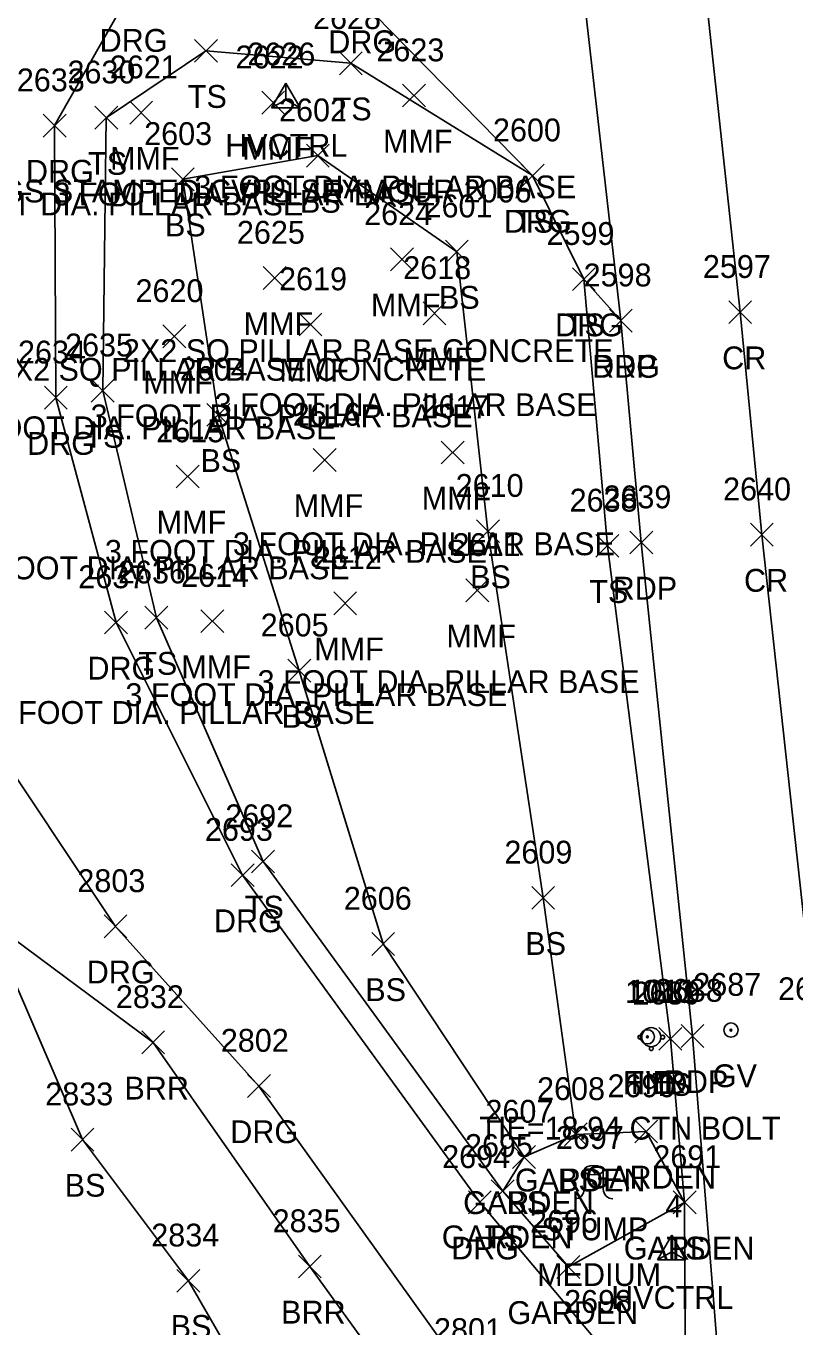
# Model space of a CAD drawing. Extents: x 1461855 to 1464118, y 556196 to 557441.
# Drawn here: x 1462324.1 to 1462391.4, y 556761.6 to 556875.5 of the extents above; entities that cross this region are included whole.
import ezdxf

# ---------------------------------------------------------------- set-up
doc = ezdxf.new("R2010")
doc.units = 0
for name, color, linetype in [('C_A', 7, 'Continuous'), ('C_C', 7, 'Continuous'), ('C_I', 7, 'Continuous'), ('CBP', 7, 'Continuous'), ('CPSM', 7, 'Continuous'), ('L_A', 7, 'Continuous'), ('L_C', 7, 'Continuous'), ('L_I', 7, 'Continuous'), ('L_TIC', 7, 'Continuous'), ('LABL', 7, 'Continuous'), ('LAPB', 7, 'Continuous'), ('LELB', 7, 'Continuous'), ('LTS', 7, 'Continuous'), ('P_A', 7, 'Continuous'), ('P_I', 7, 'Continuous'), ('P_TIC', 7, 'Continuous'), ('PET', 7, 'Continuous'), ('PRC', 7, 'Continuous'), ('R_A', 7, 'Continuous'), ('R_I', 7, 'Continuous'), ('R_TIC', 7, 'Continuous'), ('RDG', 7, 'Continuous'), ('U_A', 7, 'Continuous'), ('U_I', 7, 'Continuous'), ('UWFH', 7, 'Continuous'), ('UWV', 7, 'Continuous')]:
    doc.layers.add(name, color=color, linetype=linetype)

msp = doc.modelspace()

# ---------------------------------------------------------------- linework, layer by layer
at = {"layer": 'CBP'}
for radius in [0.625, 0.0833]:
    msp.add_circle((1462378.47, 556787.02), radius, dxfattribs=at)
at = {"layer": 'CPSM'}
for p, q in [((1462345.56, 556868.36), (1462346.81, 556870.52)), ((1462348.06, 556868.36), (1462346.81, 556870.52)), ((1462346.81, 556869.08), (1462346.81, 556870.52)), ((1462345.56, 556868.36), (1462346.81, 556869.08)), ((1462346.81, 556869.08), (1462346.81, 556869.08)), ((1462346.81, 556869.08), (1462348.06, 556868.36)), ((1462345.56, 556868.36), (1462348.06, 556868.36)), ((1462379.35, 556767.48), (1462380.6, 556769.65)), ((1462379.35, 556767.48), (1462380.6, 556769.65)), ((1462381.85, 556767.48), (1462380.6, 556769.65)), ((1462380.6, 556768.2), (1462380.6, 556769.65)), ((1462381.85, 556767.48), (1462380.6, 556769.65)), ((1462380.6, 556768.2), (1462380.6, 556769.65)), ((1462379.35, 556767.48), (1462380.6, 556768.2)), ((1462379.35, 556767.48), (1462380.6, 556768.2)), ((1462379.35, 556767.48), (1462381.85, 556767.48)), ((1462379.35, 556767.48), (1462381.85, 556767.48)), ((1462380.6, 556768.2), (1462380.6, 556768.2)), ((1462380.6, 556768.2), (1462381.85, 556767.48)), ((1462380.6, 556768.2), (1462380.6, 556768.2)), ((1462380.6, 556768.2), (1462381.85, 556767.48))]:
    msp.add_line(p, q, dxfattribs=at)
at = {"layer": 'L_TIC'}
for points in [[(1462338.82, 556872.36), (1462340.82, 556874.36)], [(1462340.82, 556872.36), (1462338.82, 556874.36)], [(1462351.5, 556871.27), (1462353.5, 556873.27)], [(1462353.5, 556871.27), (1462351.5, 556873.27)], [(1462344.71, 556867.82), (1462346.71, 556869.82)], [(1462346.71, 556867.82), (1462344.71, 556869.82)], [(1462357.04, 556868.44), (1462359.04, 556870.44)], [(1462359.04, 556868.44), (1462357.04, 556870.44)], [(1462330.09, 556866.5), (1462332.09, 556868.5)], [(1462332.09, 556866.5), (1462330.09, 556868.5)], [(1462333.14, 556866.95), (1462335.14, 556868.95)], [(1462335.14, 556866.95), (1462333.14, 556868.95)], [(1462348.61, 556863.18), (1462350.61, 556865.18)], [(1462350.61, 556863.18), (1462348.61, 556865.18)], [(1462336.79, 556861.11), (1462338.79, 556863.11)], [(1462338.79, 556861.11), (1462336.79, 556863.11)], [(1462367.42, 556861.43), (1462369.42, 556863.43)], [(1462369.42, 556861.43), (1462367.42, 556863.43)], [(1462355.98, 556854.1), (1462357.98, 556856.1)], [(1462357.98, 556854.1), (1462355.98, 556856.1)], [(1462360.78, 556854.77), (1462362.78, 556856.77)], [(1462362.78, 556854.77), (1462360.78, 556856.77)], [(1462360.78, 556854.77), (1462362.78, 556856.77)], [(1462362.78, 556854.77), (1462360.78, 556856.77)], [(1462344.84, 556852.47), (1462346.84, 556854.47)], [(1462346.84, 556852.47), (1462344.84, 556854.47)], [(1462371.91, 556852.36), (1462373.91, 556854.36)], [(1462373.91, 556852.36), (1462371.91, 556854.36)], [(1462347.97, 556848.39), (1462349.97, 556850.39)], [(1462349.97, 556848.39), (1462347.97, 556850.39)], [(1462358.83, 556849.37), (1462360.83, 556851.37)], [(1462360.83, 556849.37), (1462358.83, 556851.37)], [(1462336.05, 556847.35), (1462338.05, 556849.35)], [(1462338.05, 556847.35), (1462336.05, 556849.35)], [(1462329.78, 556842.6), (1462331.78, 556844.6)], [(1462331.78, 556842.6), (1462329.78, 556844.6)], [(1462339.9, 556840.48), (1462341.9, 556842.48)], [(1462341.9, 556840.48), (1462339.9, 556842.48)], [(1462360.42, 556837.19), (1462362.42, 556839.19)], [(1462362.42, 556837.19), (1462360.42, 556839.19)], [(1462349.21, 556836.53), (1462351.21, 556838.53)], [(1462351.21, 556836.53), (1462349.21, 556838.53)], [(1462337.21, 556835.08), (1462339.21, 556837.08)], [(1462339.21, 556835.08), (1462337.21, 556837.08)], [(1462363.51, 556830.3), (1462365.51, 556832.3)], [(1462365.51, 556830.3), (1462363.51, 556832.3)], [(1462363.51, 556830.3), (1462365.51, 556832.3)], [(1462365.51, 556830.3), (1462363.51, 556832.3)], [(1462373.97, 556829.01), (1462375.97, 556831.01)], [(1462375.97, 556829.01), (1462373.97, 556831.01)], [(1462362.58, 556825.12), (1462364.58, 556827.12)], [(1462364.58, 556825.12), (1462362.58, 556827.12)], [(1462351.01, 556823.98), (1462353.01, 556825.98)], [(1462353.01, 556823.98), (1462351.01, 556825.98)], [(1462334.48, 556822.72), (1462336.48, 556824.72)], [(1462336.48, 556822.72), (1462334.48, 556824.72)], [(1462339.38, 556822.42), (1462341.38, 556824.42)], [(1462341.38, 556822.42), (1462339.38, 556824.42)], [(1462346.99, 556818.08), (1462348.99, 556820.08)], [(1462348.99, 556818.08), (1462346.99, 556820.08)], [(1462343.82, 556801.37), (1462345.82, 556803.37)], [(1462345.82, 556801.37), (1462343.82, 556803.37)], [(1462368.34, 556798.19), (1462370.34, 556800.19)], [(1462370.34, 556798.19), (1462368.34, 556800.19)], [(1462354.33, 556794.15), (1462356.33, 556796.15)], [(1462356.33, 556794.15), (1462354.33, 556796.15)], [(1462379.48, 556785.85), (1462381.48, 556787.85)], [(1462381.48, 556785.85), (1462379.48, 556787.85)], [(1462334.19, 556785.53), (1462336.19, 556787.53)], [(1462336.19, 556785.53), (1462334.19, 556787.53)], [(1462377.37, 556777.73), (1462379.37, 556779.73)], [(1462379.37, 556777.73), (1462377.37, 556779.73)], [(1462328.01, 556777.02), (1462330.01, 556779.02)], [(1462330.01, 556777.02), (1462328.01, 556779.02)], [(1462371.2, 556777.48), (1462373.2, 556779.48)], [(1462373.2, 556777.48), (1462371.2, 556779.48)], [(1462371.2, 556777.48), (1462373.2, 556779.48)], [(1462373.2, 556777.48), (1462371.2, 556779.48)], [(1462366.67, 556775.5), (1462368.67, 556777.5)], [(1462368.67, 556775.5), (1462366.67, 556777.5)], [(1462366.67, 556775.5), (1462368.67, 556777.5)], [(1462368.67, 556775.5), (1462366.67, 556777.5)], [(1462366.67, 556775.5), (1462368.67, 556777.5)], [(1462368.67, 556775.5), (1462366.67, 556777.5)], [(1462364.8, 556772.5), (1462366.8, 556774.5)], [(1462366.8, 556772.5), (1462364.8, 556774.5)], [(1462364.8, 556772.5), (1462366.8, 556774.5)], [(1462366.8, 556772.5), (1462364.8, 556774.5)], [(1462380.73, 556771.52), (1462382.73, 556773.52)], [(1462382.73, 556771.52), (1462380.73, 556773.52)], [(1462380.73, 556771.52), (1462382.73, 556773.52)], [(1462382.73, 556771.52), (1462380.73, 556773.52)], [(1462347.92, 556765.91), (1462349.92, 556767.91)], [(1462349.92, 556765.91), (1462347.92, 556767.91)], [(1462370.55, 556765.87), (1462372.55, 556767.87)], [(1462372.55, 556765.87), (1462370.55, 556767.87)], [(1462370.55, 556765.87), (1462372.55, 556767.87)], [(1462372.55, 556765.87), (1462370.55, 556767.87)], [(1462337.28, 556764.66), (1462339.28, 556766.66)], [(1462339.28, 556764.66), (1462337.28, 556766.66)]]:
    msp.add_lwpolyline(points, dxfattribs=at)
at = {"layer": 'LABL'}
msp.add_lwpolyline([(1462266.97, 556912.47), (1462274.52, 556891.23), (1462280.07, 556865.7), (1462289.54, 556828.05), (1462304.73, 556803.64), (1462320.72, 556797.25), (1462335.19, 556786.53), (1462348.92, 556766.91), (1462363.68, 556746.45), (1462353.82, 556738.72), (1462344.08, 556725.82), (1462329.22, 556725.69), (1462313.32, 556709.65), (1462319.88, 556687.65), (1462319.87, 556671.79), (1462309.53, 556658.61)], dxfattribs=at)
at = {"layer": 'LAPB'}
for points in [[(1462367.67, 556776.5), (1462372.2, 556778.48), (1462378.37, 556778.73), (1462381.73, 556772.52), (1462371.55, 556766.87)], [(1462367.67, 556776.5), (1462365.8, 556773.5), (1462371.55, 556766.87)]]:
    msp.add_lwpolyline(points, dxfattribs=at)
at = {"layer": 'LELB'}
for points in [[(1462298.79, 556927.09), (1462302.53, 556917.21), (1462305.12, 556905.68), (1462302.57, 556876.56), (1462305.98, 556856.21), (1462308.29, 556833.25), (1462314.59, 556815.41), (1462320.72, 556797.25), (1462329.01, 556778.02), (1462338.28, 556765.66), (1462353.82, 556738.72), (1462367.21, 556725.65), (1462382.15, 556699.86)], [(1462368.42, 556862.43), (1462352.5, 556872.27), (1462339.82, 556873.36), (1462331.09, 556867.5), (1462330.78, 556843.6), (1462335.48, 556823.72), (1462344.82, 556802.37), (1462365.8, 556773.5)], [(1462361.78, 556855.77), (1462349.61, 556864.18), (1462337.79, 556862.11), (1462340.9, 556841.48), (1462347.99, 556819.08), (1462355.33, 556795.15), (1462367.67, 556776.5)], [(1462361.78, 556855.77), (1462364.51, 556831.3)], [(1462372.91, 556853.36), (1462374.97, 556830.01), (1462380.48, 556786.85), (1462381.73, 556772.52), (1462381.8, 556754.73)], [(1462372.2, 556778.48), (1462369.34, 556799.19), (1462364.51, 556831.3)]]:
    msp.add_lwpolyline(points, dxfattribs=at)
at = {"layer": 'LTS'}
for p, q in [((1462372.94, 556775.34), (1462372.94, 556773.67)), ((1462374.6, 556775.17), (1462374.6, 556775.34)), ((1462374.6, 556775.34), (1462374.6, 556773.67)), ((1462373.77, 556774.2), (1462373.77, 556774.2)), ((1462373.77, 556774.2), (1462373.77, 556774.2)), ((1462373.77, 556774.17), (1462373.77, 556774.17))]:
    msp.add_line(p, q, dxfattribs=at)
msp.add_circle((1462373.77, 556774.2), 0.0833, dxfattribs=at)
for centre, start, end in [((1462372.1, 556773.67), 270, 360), ((1462375.44, 556773.67), 180, 270)]:
    msp.add_arc(centre, 0.833, start, end, dxfattribs=at)
msp.add_ellipse((1462373.77, 556775.34), major_axis=(-0.833, 0), ratio=0.5, dxfattribs=at)
at = {"layer": 'P_TIC'}
for points in [[(1462385.59, 556849.47), (1462387.59, 556851.47)], [(1462387.59, 556849.47), (1462385.59, 556851.47)], [(1462375.15, 556848.73), (1462377.15, 556850.73)], [(1462377.15, 556848.73), (1462375.15, 556850.73)], [(1462376.94, 556829.3), (1462378.94, 556831.3)], [(1462378.94, 556829.3), (1462376.94, 556831.3)], [(1462387.49, 556829.99), (1462389.49, 556831.99)], [(1462389.49, 556829.99), (1462387.49, 556831.99)], [(1462381.42, 556786.09), (1462383.42, 556788.09)], [(1462383.42, 556786.09), (1462381.42, 556788.09)]]:
    msp.add_lwpolyline(points, dxfattribs=at)
at = {"layer": 'PET'}
msp.add_lwpolyline([(1462362.03, 557020.04), (1462364.05, 556983.23), (1462364.4, 556972.86), (1462366.43, 556947.21), (1462369.72, 556911.82), (1462372.49, 556881.81), (1462376.15, 556849.73), (1462377.94, 556830.3), (1462382.42, 556787.09), (1462384.86, 556756.35), (1462386.15, 556741.35), (1462389.31, 556702.38), (1462390.63, 556682.52), (1462394.11, 556641.35), (1462397.73, 556598.46)], dxfattribs=at)
at = {"layer": 'PRC'}
msp.add_lwpolyline([(1462372.67, 557021), (1462375.13, 556983.57), (1462377.28, 556947.87), (1462380.67, 556912.86), (1462383.06, 556883.19), (1462386.59, 556850.47), (1462388.49, 556830.99), (1462393.27, 556787.23), (1462396.72, 556743.28), (1462399.49, 556711.38), (1462401.67, 556680.3), (1462405.06, 556640.86), (1462409.08, 556598.37)], dxfattribs=at)
at = {"layer": 'R_TIC'}
for points in [[(1462325.57, 556865.81), (1462327.57, 556867.81)], [(1462327.57, 556865.81), (1462325.57, 556867.81)], [(1462367.42, 556861.43), (1462369.42, 556863.43)], [(1462369.42, 556861.43), (1462367.42, 556863.43)], [(1462371.91, 556852.36), (1462373.91, 556854.36)], [(1462373.91, 556852.36), (1462371.91, 556854.36)], [(1462375.15, 556848.73), (1462377.15, 556850.73)], [(1462377.15, 556848.73), (1462375.15, 556850.73)], [(1462325.67, 556841.98), (1462327.67, 556843.98)], [(1462327.67, 556841.98), (1462325.67, 556843.98)], [(1462330.95, 556822.3), (1462332.95, 556824.3)], [(1462332.95, 556822.3), (1462330.95, 556824.3)], [(1462342.03, 556800.18), (1462344.03, 556802.18)], [(1462344.03, 556800.18), (1462342.03, 556802.18)], [(1462330.9, 556795.69), (1462332.9, 556797.69)], [(1462332.9, 556795.69), (1462330.9, 556797.69)], [(1462343.46, 556781.71), (1462345.46, 556783.71)], [(1462345.46, 556781.71), (1462343.46, 556783.71)], [(1462362.8, 556771.53), (1462364.8, 556773.53)], [(1462364.8, 556771.53), (1462362.8, 556773.53)]]:
    msp.add_lwpolyline(points, dxfattribs=at)
at = {"layer": 'RDG'}
for points in [[(1462389.31, 556702.38), (1462382.82, 556722.74), (1462375.16, 556739.02), (1462362.56, 556757.38), (1462344.46, 556782.71), (1462331.9, 556796.69), (1462320.22, 556814.15), (1462314.76, 556835.2), (1462311.82, 556859.76), (1462312.08, 556892.51), (1462314.63, 556919.62), (1462308.29, 556930.67)], [(1462376.15, 556849.73), (1462372.91, 556853.36), (1462368.42, 556862.43), (1462353.04, 556878.15), (1462343.64, 556880.74), (1462333.03, 556878.27), (1462326.57, 556866.81), (1462326.67, 556842.98), (1462331.95, 556823.3), (1462343.03, 556801.18), (1462363.8, 556772.53), (1462374.49, 556759.85), (1462381.8, 556754.73), (1462384.86, 556756.35)]]:
    msp.add_lwpolyline(points, dxfattribs=at)
at = {"layer": 'UWFH'}
msp.add_line((1462378.81, 556786.99), (1462378.81, 556786.99), dxfattribs=at)
for centre, radius in [((1462378.81, 556786.99), 0.833), ((1462377.81, 556786.99), 0.167), ((1462379.81, 556786.99), 0.167), ((1462378.81, 556785.99), 0.167)]:
    msp.add_circle(centre, radius, dxfattribs=at)
at = {"layer": 'UWV'}
for radius in [0.625, 0.0833]:
    msp.add_circle((1462385.79, 556787.61), radius, dxfattribs=at)

# ---------------------------------------------------------------- texts
at = {"layer": 'C_A'}
for s, p in [('HVCTRL', (1462341.5, 556864.08)), ('TIE', (1462376.55, 556782.02)), ('HVCTRL', (1462375.3, 556763.2)), ('HVCTRL', (1462375.3, 556763.2))]:
    msp.add_text(s, height=2, dxfattribs=at).set_placement(p)
at = {"layer": 'C_C'}
for s, p in [('VTGS STAMPED CVPS SEYMOUR 2006', (1462318.39, 556860.08)), ('TIE=18.94 CTN BOLT', (1462363.75, 556778.02))]:
    msp.add_text(s, height=2, dxfattribs=at).set_placement(p)
at = {"layer": 'C_I'}
for s, p in [('2626', (1462343.44, 556872.08)), ('1011', (1462376.83, 556790.02)), ('4', (1462380.04, 556771.2)), ('4', (1462380.04, 556771.2))]:
    msp.add_text(s, height=2, dxfattribs=at).set_placement(p)
at = {"layer": 'L_A'}
for s, p in [('TS', (1462338.23, 556868.36)), ('TS', (1462350.91, 556867.27)), ('MMF', (1462355.33, 556864.44)), ('MMF', (1462343, 556863.82)), ('TS', (1462329.5, 556862.5)), ('MMF', (1462331.42, 556862.95)), ('BS', (1462348.05, 556859.18)), ('TS', (1462366.83, 556857.43)), ('BS', (1462336.23, 556857.11)), ('BS', (1462360.22, 556850.77)), ('BS', (1462360.22, 556850.77)), ('MMF', (1462354.26, 556850.1)), ('MMF', (1462343.12, 556848.47)), ('TS', (1462371.32, 556848.36)), ('MMF', (1462357.11, 556845.37)), ('MMF', (1462346.25, 556844.39)), ('MMF', (1462334.33, 556843.35)), ('TS', (1462329.19, 556838.6)), ('BS', (1462339.34, 556836.48)), ('MMF', (1462347.5, 556832.53)), ('MMF', (1462358.71, 556833.19)), ('MMF', (1462335.5, 556831.08)), ('BS', (1462362.95, 556826.3)), ('BS', (1462362.95, 556826.3)), ('TS', (1462373.38, 556825.01)), ('MMF', (1462360.87, 556821.12)), ('MMF', (1462349.3, 556819.98)), ('TS', (1462333.89, 556818.72)), ('MMF', (1462337.66, 556818.42)), ('BS', (1462346.44, 556814.08)), ('TS', (1462343.22, 556797.37)), ('BS', (1462367.78, 556794.19)), ('BS', (1462353.77, 556790.15)), ('BRR', (1462332.68, 556781.53)), ('TS', (1462378.89, 556781.85)), ('GARDEN', (1462366.87, 556773.48)), ('BS', (1462370.64, 556773.48)), ('GARDEN', (1462373.04, 556773.73)), ('BS', (1462327.45, 556773.02)), ('GARDEN', (1462362.34, 556771.5)), ('GARDEN', (1462362.34, 556771.5)), ('BS', (1462366.12, 556771.5)), ('GARDEN', (1462360.47, 556768.5)), ('TS', (1462364.21, 556768.5)), ('STUMP', (1462369.19, 556769.2)), ('GARDEN', (1462376.4, 556767.52)), ('TS', (1462380.14, 556767.52)), ('BRR', (1462346.4, 556761.91)), ('GARDEN', (1462366.22, 556761.87)), ('GARDEN', (1462366.22, 556761.87)), ('BS', (1462336.73, 556760.66))]:
    msp.add_text(s, height=2, dxfattribs=at).set_placement(p)
at = {"layer": 'L_C'}
for s, p in [('3 FOOT DIA. PILLAR BASE', (1462326.47, 556859.82)), ('3 FOOT DIA. PILLAR BASE', (1462338.8, 556860.44)), ('3 FOOT DIA. PILLAR BASE', (1462314.9, 556858.95)), ('2X2 SQ PILLAR BASE CONCRETE', (1462332.55, 556846.1)), ('2X2 SQ PILLAR BASE CONCRETE', (1462321.41, 556844.47)), ('3 FOOT DIA. PILLAR BASE', (1462329.72, 556840.39)), ('3 FOOT DIA. PILLAR BASE', (1462340.58, 556841.37)), ('3 FOOT DIA. PILLAR BASE', (1462317.8, 556839.35)), ('3 FOOT DIA. PILLAR BASE', (1462342.18, 556829.19)), ('3 FOOT DIA. PILLAR BASE', (1462330.97, 556828.53)), ('3 FOOT DIA. PILLAR BASE', (1462318.97, 556827.08)), ('3 FOOT DIA. PILLAR BASE', (1462344.34, 556817.12)), ('3 FOOT DIA. PILLAR BASE', (1462332.77, 556815.98)), ('3 FOOT DIA. PILLAR BASE', (1462321.14, 556814.42)), ('MEDIUM', (1462368.82, 556765.2))]:
    msp.add_text(s, height=2, dxfattribs=at).set_placement(p)
at = {"layer": 'L_I'}
for s, p in [('2628', (1462349.19, 556875.27)), ('2623', (1462354.74, 556872.44)), ('2622', (1462342.41, 556871.82)), ('2630', (1462327.69, 556870.5)), ('2621', (1462331.4, 556870.95)), ('2602', (1462346.22, 556867.18)), ('2600', (1462364.95, 556865.43)), ('2603', (1462334.41, 556865.11)), ('2601', (1462358.96, 556858.77)), ('2601', (1462358.96, 556858.77)), ('2624', (1462353.67, 556858.1)), ('2625', (1462342.53, 556856.47)), ('2599', (1462369.64, 556856.36)), ('2618', (1462357.09, 556853.37)), ('2619', (1462346.22, 556852.39)), ('2620', (1462333.65, 556851.35)), ('2635', (1462327.48, 556846.6)), ('2604', (1462337.52, 556844.48)), ('2616', (1462347.42, 556840.53)), ('2617', (1462358.68, 556841.19)), ('2615', (1462335.47, 556839.08)), ('2610', (1462361.68, 556834.3)), ('2610', (1462361.68, 556834.3)), ('2638', (1462371.66, 556833.01)), ('2611', (1462361.41, 556829.12)), ('2612', (1462349.27, 556827.98)), ('2636', (1462332.12, 556826.72)), ('2614', (1462337.64, 556826.42)), ('2605', (1462344.61, 556822.08)), ('2692', (1462341.51, 556805.37)), ('2609', (1462365.95, 556802.19)), ('2606', (1462351.89, 556798.15)), ('2832', (1462331.93, 556789.53)), ('2689', (1462377.17, 556789.85)), ('2833', (1462325.75, 556781.02)), ('2608', (1462368.81, 556781.48)), ('2608', (1462368.81, 556781.48)), ('2690', (1462374.98, 556781.73)), ('2607', (1462364.29, 556779.5)), ('2607', (1462364.29, 556779.5)), ('2607', (1462364.29, 556779.5)), ('2695', (1462362.5, 556776.5)), ('2695', (1462362.5, 556776.5)), ('2697', (1462370.46, 556777.2)), ('2691', (1462378.99, 556775.52)), ('2691', (1462378.99, 556775.52)), ('2835', (1462345.66, 556769.91)), ('2696', (1462368.19, 556769.87)), ('2696', (1462368.19, 556769.87)), ('2834', (1462335.03, 556768.66))]:
    msp.add_text(s, height=2, dxfattribs=at).set_placement(p)
at = {"layer": 'P_A'}
for s, p in [('CR', (1462385.02, 556845.47)), ('RDP', (1462373.63, 556844.73)), ('CR', (1462386.93, 556825.99)), ('RDP', (1462375.43, 556825.3)), ('RDP', (1462379.91, 556782.09))]:
    msp.add_text(s, height=2, dxfattribs=at).set_placement(p)
at = {"layer": 'P_I'}
for s, p in [('2597', (1462383.33, 556853.47)), ('2598', (1462372.89, 556852.73)), ('2640', (1462385.1, 556833.99)), ('2639', (1462374.62, 556833.3)), ('2686', (1462389.91, 556790.23)), ('2688', (1462379.12, 556790.09))]:
    msp.add_text(s, height=2, dxfattribs=at).set_placement(p)
at = {"layer": 'R_A'}
for p in [(1462330.51, 556873.27), (1462350.53, 556873.15), (1462324.06, 556861.81), (1462365.91, 556857.43), (1462370.39, 556848.36), (1462373.63, 556844.73), (1462324.16, 556837.98), (1462329.44, 556818.3), (1462340.52, 556796.18), (1462329.38, 556791.69), (1462341.95, 556777.71), (1462361.29, 556767.53)]:
    msp.add_text('DRG', height=2, dxfattribs=at).set_placement(p)
at = {"layer": 'R_I'}
for s, p in [('2633', (1462323.26, 556869.81)), ('2600', (1462364.95, 556865.43)), ('2599', (1462369.64, 556856.36)), ('2598', (1462372.89, 556852.73)), ('2634', (1462323.36, 556845.98)), ('2637', (1462328.64, 556826.3)), ('2693', (1462339.73, 556804.18)), ('2803', (1462328.56, 556799.69)), ('2802', (1462341.12, 556785.71)), ('2694', (1462360.5, 556775.53)), ('2698', (1462371.18, 556762.85)), ('2801', (1462359.79, 556760.38))]:
    msp.add_text(s, height=2, dxfattribs=at).set_placement(p)
at = {"layer": 'U_A'}
for s, p in [('GV', (1462384.2, 556782.61)), ('HYD', (1462376.33, 556781.99))]:
    msp.add_text(s, height=2, dxfattribs=at).set_placement(p)
at = {"layer": 'U_I'}
for s, p in [('2687', (1462382.49, 556790.61)), ('1010', (1462376.52, 556789.99))]:
    msp.add_text(s, height=2, dxfattribs=at).set_placement(p)

doc.saveas('drawing.dxf')
